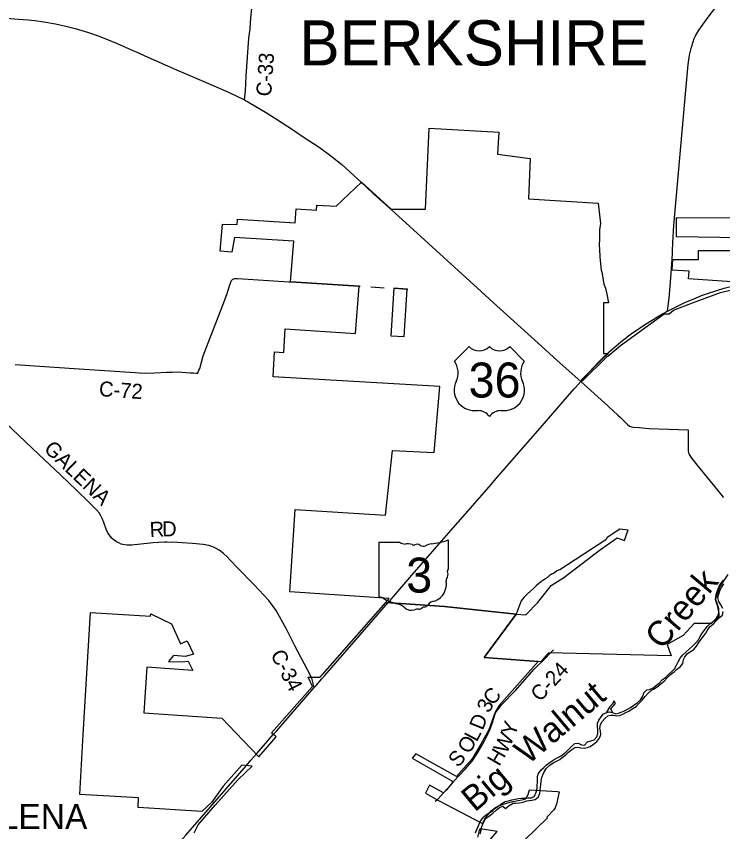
# Model space of a CAD drawing. Extents: x 1674899 to 2057726, y 653888 to 988278.
# Drawn here: x 1855438 to 1869524, y 809139 to 825391 of the extents above; entities that cross this region are included whole.
import ezdxf

# ---------------------------------------------------------------- set-up
doc = ezdxf.new("R2010")
doc.units = 0
for name, color, linetype in [('GM_X_Corporation', 7, 'Continuous'), ('GM_X_Corporation_Text', 7, 'Continuous'), ('GM_X_County_Road', 7, 'Continuous'), ('GM_X_County_Road_Text', 7, 'Continuous'), ('GM_X_Major_River', 7, 'Continuous'), ('GM_X_Major_River_Text', 7, 'Continuous'), ('GM_X_State_Location', 7, 'Continuous'), ('GM_X_State_Route', 7, 'Continuous'), ('GM_X_State_Shield', 7, 'Continuous'), ('GM_X_Township_Text', 7, 'Continuous'), ('GM_X_US_Location', 7, 'Continuous'), ('GM_X_US_Route', 7, 'Continuous'), ('GM_X_US_Shield', 7, 'Continuous'), ('SH_Data', 7, 'Continuous')]:
    doc.layers.add(name, color=color, linetype=linetype)

msp = doc.modelspace()

# ---------------------------------------------------------------- linework, layer by layer
at = {"layer": 'GM_X_Corporation'}
for points in [[(1869626, 814263), (1869472, 814042), (1869383, 813776), (1869438, 813593), (1869447, 813422), (1869302, 813286), (1868954, 813287), (1868735, 813050), (1868415, 812867), (1868495, 812643), (1866054, 812701), (1865997, 812642), (1865896, 812527), (1865843, 812531), (1864768, 812610), (1865403, 813477), (1863975, 813629), (1862805, 813710), (1862871, 813787), (1860894, 813922), (1860996, 815560), (1862803, 815449), (1862941, 816737), (1863769, 816697), (1863883, 818014), (1860562, 818202), (1860587, 818701), (1860771, 818691), (1860802, 819164), (1862199, 819069), (1862276, 820013), (1860906, 820099), (1860970, 820906), (1859791, 820983), (1859738, 820687), (1859505, 820707), (1859552, 821251), (1859841, 821244), (1859848, 821345), (1860999, 821277), (1861021, 821551), (1861422, 821527), (1861430, 821628), (1861816, 821605), (1862321, 822084), (1862912, 821546), (1863596, 821544), (1863668, 823164), (1865058, 823080), (1865034, 822645), (1865687, 822560), (1865651, 821750), (1867041, 821665), (1867085, 821260), (1867068, 821136), (1867065, 820962), (1867060, 820821), (1867068, 820747), (1867072, 820594), (1867087, 820460), (1867100, 820333), (1867115, 820300), (1867151, 820053), (1867187, 819974), (1867212, 819855), (1867245, 819678), (1867145, 819678), (1867148, 818668), (1867246, 818668), (1867161, 818594), (1866699, 818140), (1866722, 818118), (1867219, 818607), (1867231, 818617), (1867484, 818828), (1868360, 819462), (1868454, 819464), (1868541, 819536), (1868921, 819679), (1869480, 819883), (1869917, 819994)], [(1869899, 820974), (1868600, 820997), (1868600, 821384), (1871245, 821376)], [(1869899, 820085), (1868844, 820159), (1868852, 820309), (1868513, 820332), (1868528, 820542), (1869039, 820542), (1869039, 820726), (1869899, 820726)], [(1858983, 809113), (1859065, 809276), (1859404, 809666), (1859863, 810176), (1860139, 810448), (1859933, 810468), (1859566, 810043), (1859327, 809721), (1859138, 809540), (1857865, 809621), (1857876, 809816), (1856704, 809881), (1856773, 811076), (1856914, 813505), (1858114, 813436), (1858118, 813482), (1858535, 813283), (1858712, 812884), (1858845, 812940), (1858970, 812675), (1858813, 812629), (1858574, 812648), (1858471, 812534), (1858741, 812523), (1858864, 812540), (1858957, 812354), (1858043, 812416), (1857978, 811505), (1859535, 811404), (1859815, 811112), (1860275, 810628), (1860621, 811028), (1860529, 811110), (1861344, 812036), (1861260, 812216), (1861498, 812216), (1862805, 813710), (1863975, 813629), (1865403, 813477), (1864768, 812610), (1865843, 812531), (1865065, 811655), (1864989, 811518), (1864863, 811170), (1864701, 810884), (1864525, 810591), (1864418, 810465), (1864215, 810236), (1863402, 810688), (1863333, 810602), (1864120, 810151), (1864151, 810133), (1864012, 809966), (1863958, 809914), (1863680, 810064), (1863595, 809906), (1863859, 809760), (1864733, 809304), (1864786, 809405), (1864823, 809458), (1864864, 809499), (1864909, 809555), (1864976, 809609), (1865042, 809648), (1865212, 809706), (1865339, 809742), (1865409, 809752), (1865553, 809778), (1865590, 809795), (1865610, 809820), (1865642, 809877), (1865672, 809975), (1866230, 809941), (1866265, 809936), (1866212, 809686), (1866193, 809633), (1866180, 809613), (1866156, 809577), (1866016, 809430), (1866027, 809418), (1865570, 808968)], [(1864871, 808960), (1865028, 809140), (1864686, 809196), (1864670, 809164), (1864633, 809031)]]:
    msp.add_lwpolyline(points, dxfattribs=at)
for points in [[(1862906, 819024), (1863171, 819007), (1863230, 819954), (1862964, 819970)], [(1865403, 813477), (1865595, 813463), (1865838, 813709), (1866105, 814049), (1866357, 814208), (1867086, 814766), (1867421, 814993), (1867566, 814942), (1867606, 815063), (1867642, 815146), (1867470, 815167), (1867221, 815005), (1867191, 814953), (1866273, 814357), (1866252, 814350), (1866224, 814337), (1866188, 814318), (1866148, 814284), (1866111, 814270), (1866070, 814243), (1866027, 814208), (1865989, 814179), (1865937, 814144), (1865899, 814117), (1865853, 814081), (1865802, 814037), (1865749, 813986), (1865694, 813935), (1865628, 813870), (1865561, 813807), (1865503, 813738)]]:
    msp.add_lwpolyline(points, close=True, dxfattribs=at)
at = {"layer": 'GM_X_County_Road'}
for points in [[(1859988, 823723), (1860006, 823907), (1860023, 824199), (1860075, 824953), (1860102, 825144), (1860114, 825358), (1860137, 825544)], [(1855415, 818448), (1856692, 818365), (1857805, 818293), (1857887, 818287), (1857997, 818281), (1858195, 818286), (1858439, 818296), (1858547, 818299), (1858647, 818302), (1858736, 818299), (1858909, 818286), (1858969, 818282), (1859024, 818279), (1859060, 818281), (1859080, 818337), (1859095, 818374), (1859163, 818625), (1859262, 818885), (1859464, 819395), (1859545, 819601), (1859637, 819846), (1859697, 820038), (1859727, 820125), (1859753, 820151), (1859775, 820161), (1859787, 820164), (1859852, 820165), (1860873, 820101)], [(1860873, 820101), (1860906, 820099), (1862276, 820013), (1862296, 820012)], [(1862506, 819999), (1862509, 819999), (1862770, 819982)], [(1862980, 819969), (1863230, 819954), (1863244, 819953)], [(1857182, 815299), (1857153, 815378), (1857124, 815436), (1857089, 815491), (1857039, 815553), (1856865, 815727), (1856650, 815933), (1856316, 816250), (1855886, 816655), (1854135, 818318), (1853948, 818496), (1853892, 818538)], [(1858745, 814899), (1858660, 814905), (1858449, 814910), (1858391, 814909), (1858164, 814898), (1857861, 814864), (1857798, 814856), (1857739, 814849), (1857648, 814850), (1857559, 814865), (1857530, 814873), (1857479, 814893), (1857433, 814917), (1857388, 814948), (1857347, 814984), (1857307, 815028), (1857257, 815108), (1857229, 815169), (1857182, 815299)], [(1861324, 812212), (1861236, 812378), (1860992, 812846), (1860828, 813174), (1860617, 813548), (1860476, 813746), (1860173, 814063), (1859848, 814400), (1859708, 814543), (1859640, 814615), (1859568, 814682), (1859482, 814748), (1859421, 814784), (1859356, 814815), (1859277, 814840), (1859165, 814861), (1858949, 814884), (1858745, 814899)], [(1864113, 810086), (1864158, 810136), (1864387, 810382), (1864526, 810545), (1864640, 810718), (1864769, 810937), (1864875, 811146), (1864930, 811298), (1864995, 811506), (1865050, 811588), (1865117, 811671), (1865392, 811956), (1865763, 812377), (1866002, 812614)], [(1866002, 812614), (1866066, 812677), (1866122, 812737), (1866148, 812764)], [(1861379, 812013), (1861332, 812198), (1861324, 812212)], [(1863902, 809854), (1863958, 809914), (1864113, 810086)], [(1863789, 809745), (1863841, 809789), (1863902, 809854)]]:
    msp.add_lwpolyline(points, dxfattribs=at)
at = {"layer": 'GM_X_Major_River'}
for points in [[(1868988, 812905), (1869040, 812965), (1869073, 813027), (1869117, 813093), (1869163, 813157), (1869214, 813227), (1869270, 813284), (1869341, 813338), (1869399, 813392), (1869439, 813458), (1869446, 813522), (1869436, 813586), (1869422, 813650), (1869403, 813701), (1869381, 813767), (1869385, 813833), (1869410, 813905), (1869432, 813979), (1869455, 814033), (1869485, 814085), (1869539, 814155)], [(1869524, 813590), (1869486, 813662), (1869445, 813729), (1869429, 813805), (1869446, 813873), (1869470, 813941), (1869498, 814009), (1869549, 814079)], [(1869004, 812835), (1869046, 812909), (1869096, 812975), (1869145, 813043), (1869185, 813095), (1869229, 813166), (1869272, 813228), (1869338, 813280), (1869399, 813346), (1869457, 813406), (1869517, 813453), (1869532, 813526)], [(1864597, 809114), (1864622, 809180), (1864648, 809242), (1864677, 809308), (1864701, 809362), (1864759, 809432), (1864822, 809487), (1864892, 809531), (1864942, 809559), (1865002, 809615), (1865065, 809664), (1865117, 809702), (1865189, 809742), (1865253, 809755), (1865321, 809773), (1865383, 809787), (1865449, 809802), (1865512, 809810), (1865580, 809810), (1865646, 809811), (1865714, 809813), (1865774, 809845), (1865804, 809929), (1865821, 809997), (1865827, 810061), (1865833, 810123), (1865832, 810191), (1865832, 810245), (1865848, 810299), (1865903, 810369), (1865957, 810417), (1866007, 810463), (1866060, 810507), (1866126, 810554), (1866186, 810588), (1866260, 810628), (1866327, 810669), (1866395, 810727), (1866447, 810775), (1866510, 810839), (1866578, 810898), (1866642, 810900), (1866708, 810868), (1866770, 810865), (1866826, 810933), (1866892, 810947), (1866958, 810968), (1867011, 811030), (1867033, 811094), (1867034, 811162), (1867028, 811235), (1867026, 811301), (1867055, 811361), (1867099, 811425), (1867147, 811487), (1867198, 811510), (1867262, 811528), (1867326, 811514), (1867392, 811491), (1867444, 811501), (1867496, 811519), (1867566, 811550), (1867626, 811578), (1867684, 811616), (1867755, 811661), (1867821, 811707), (1867883, 811765), (1867930, 811839), (1867950, 811907), (1868010, 811963), (1868064, 811972), (1868137, 812008), (1868187, 812044), (1868255, 812100), (1868318, 812163), (1868388, 812221), (1868450, 812279), (1868507, 812331), (1868565, 812388), (1868603, 812460), (1868634, 812522), (1868676, 812598), (1868732, 812662), (1868789, 812718), (1868859, 812786), (1868922, 812839), (1868988, 812905)], [(1864689, 809093), (1864706, 809167), (1864722, 809239), (1864742, 809289), (1864765, 809347), (1864803, 809409), (1864875, 809453), (1864938, 809505), (1865004, 809568), (1865072, 809624), (1865139, 809648), (1865196, 809599), (1865267, 809659), (1865343, 809709), (1865393, 809710), (1865469, 809712), (1865545, 809728), (1865615, 809751), (1865665, 809759), (1865719, 809769), (1865787, 809782), (1865850, 809836), (1865878, 809906), (1865881, 809974), (1865889, 810024), (1865895, 810076), (1865902, 810143), (1865920, 810217), (1865934, 810271), (1865967, 810335), (1866011, 810405), (1866079, 810468), (1866144, 810510), (1866212, 810546), (1866274, 810581), (1866324, 810619), (1866393, 810671), (1866451, 810725), (1866515, 810775), (1866578, 810818), (1866630, 810822), (1866693, 810808), (1866763, 810803), (1866828, 810819), (1866878, 810839), (1866946, 810884), (1867012, 810936), (1867065, 811002), (1867091, 811074), (1867087, 811142), (1867074, 811204), (1867084, 811272), (1867119, 811336), (1867173, 811392), (1867231, 811446), (1867295, 811464), (1867347, 811463), (1867415, 811445), (1867465, 811453), (1867533, 811478), (1867594, 811512), (1867650, 811538), (1867718, 811587), (1867796, 811632), (1867857, 811698), (1867919, 811761), (1867980, 811833), (1868040, 811902), (1868104, 811962), (1868158, 811987), (1868243, 812048), (1868289, 812089), (1868359, 812141), (1868418, 812205), (1868482, 812273), (1868553, 812328), (1868603, 812370), (1868675, 812424), (1868732, 812492), (1868742, 812568), (1868770, 812622), (1868823, 812690), (1868897, 812735), (1868951, 812773), (1869004, 812835)], [(1867326, 811514), (1867293, 811587), (1867339, 811640), (1867389, 811692), (1867359, 811750), (1867323, 811680), (1867269, 811621), (1867198, 811510)], [(1867198, 811510), (1867262, 811528), (1867326, 811514)]]:
    msp.add_lwpolyline(points, dxfattribs=at)
at = {"layer": 'GM_X_State_Route'}
for points in [[(1868532, 820875), (1868550, 821219), (1868792, 823921), (1868838, 824429), (1868865, 824617), (1868879, 824699), (1868899, 824776), (1868933, 824884), (1868958, 824946), (1868978, 824987), (1869049, 825113), (1869236, 825376), (1869514, 825748)], [(1868523, 820718), (1868532, 820875)], [(1868515, 820560), (1868520, 820663), (1868523, 820718)], [(1868423, 819513), (1868436, 819621), (1868455, 819771), (1868478, 820007), (1868509, 820452), (1868515, 820560)], [(1866346, 817716), (1866565, 817968), (1866588, 817993)], [(1866588, 817993), (1866693, 818111)], [(1866693, 818111), (1867234, 817626), (1867256, 817606)], [(1864967, 816131), (1865275, 816485), (1865884, 817183), (1866346, 817716)], [(1867256, 817606), (1867435, 817444), (1867478, 817401)], [(1867478, 817401), (1867625, 817254), (1867664, 817220), (1867706, 817207), (1867748, 817201), (1867855, 817194)], [(1867855, 817194), (1867983, 817185), (1868056, 817177)], [(1868056, 817177), (1868448, 817163), (1868836, 817146)], [(1868836, 817146), (1868837, 816776)], [(1868837, 816776), (1868837, 816721), (1868851, 816673), (1868887, 816606), (1869030, 816427), (1869071, 816377)], [(1869071, 816377), (1869420, 815948), (1869509, 815839), (1869530, 815808), (1869534, 815802)], [(1862967, 813834), (1863287, 814202), (1863966, 814984), (1864395, 815476), (1864911, 816067), (1864967, 816131)], [(1861588, 812249), (1862256, 813018), (1862855, 813706), (1862898, 813755)], [(1862898, 813755), (1862922, 813783), (1862967, 813834)], [(1861414, 812052), (1861532, 812184), (1861588, 812249)], [(1860617, 811135), (1860632, 811151), (1860959, 811525), (1861379, 812013), (1861414, 812052)], [(1860234, 810698), (1860366, 810850), (1860563, 811079), (1860617, 811135)], [(1860025, 810459), (1860116, 810563), (1860234, 810698)], [(1853225, 794338), (1854573, 800349), (1855512, 804546), (1855541, 804679), (1855596, 804898), (1855689, 805139), (1855836, 805465), (1855908, 805599), (1856008, 805767), (1856148, 805978), (1856255, 806119), (1856504, 806413), (1857597, 807668), (1858467, 808668), (1858818, 809072), (1859440, 809788), (1860025, 810459)]]:
    msp.add_lwpolyline(points, dxfattribs=at)
at = {"layer": 'GM_X_State_Shield'}
for p, q in [((1862667, 814887), (1862667, 813831)), ((1863089, 814906), (1862681, 814906)), ((1864059, 814379), (1864059, 814932)), ((1864059, 814379), (1864059, 814379))]:
    msp.add_line(p, q, dxfattribs=at)
for centre, radius, start, end in [((1862683, 814890), 16.1, 98.1301, 188.1301), ((1863186, 815028), 156, 231.6195, 271.1119), ((1863564, 816346), 1476, 275.8445, 288.9065), ((1864044, 814934), 15.5, 351.8621, 97.738), ((1863238, 814312), 562, 80.4867, 94.9883), ((1863365, 814895), 45.1, 219.7921, 297.1024), ((1863431, 814773), 93.8, 54.4667, 119.1411), ((1863553, 814940), 113, 233.8562, 294.8282), ((1863752, 814583), 297, 97.3462, 120.7689), ((1864056, 814338), 24, 107.944, 210.337), ((1863903, 814269), 144, 340.033, 23.6496), ((1864043, 814377), 16.6, 289.6038, 7.7341), ((1863646, 814077), 369, 292.3089, 8.9858), ((1864115, 814148), 105, 136.8065, 186.9296), ((1862683, 813828), 16.3, 171.9584, 258.3066), ((1862686, 813937), 124, 267.339, 280.6039), ((1862711, 813770), 44.8, 29.7484, 93.2717), ((1863277, 814719), 1066, 240.4129, 257.1985), ((1862959, 813356), 334, 47.1842, 75.836), ((1863319, 813765), 212, 230.7004, 286.2918), ((1863457, 813685), 113, 268.777, 315.5493), ((1863559, 813583), 31.8, 65.7517, 132.6484), ((1863546, 813728), 119, 282.8732, 323.2771), ((1863802, 813534), 202, 94.4031, 142.5768), ((1863442, 813399), 174, 85.6951, 111.2099)]:
    msp.add_arc(centre, radius, start, end, dxfattribs=at)
at = {"layer": 'GM_X_US_Route'}
for points in [[(1855037, 825370), (1855173, 825360), (1855248, 825354), (1855476, 825337), (1855674, 825320), (1855808, 825306), (1855988, 825281), (1856219, 825240), (1856454, 825186), (1856610, 825146), (1856879, 825067), (1857093, 824992), (1857448, 824848), (1857746, 824717), (1857872, 824661)], [(1857872, 824661), (1858002, 824603), (1858452, 824407), (1858634, 824327), (1858849, 824233), (1859315, 824029), (1859681, 823869), (1859988, 823723), (1860406, 823477), (1860588, 823365), (1860963, 823124), (1861157, 822990), (1861474, 822783), (1861713, 822608), (1861927, 822435), (1862088, 822291), (1862329, 822071), (1862359, 822043)], [(1862359, 822043), (1862416, 821990), (1862570, 821847), (1862984, 821471)], [(1862984, 821471), (1864255, 820317), (1864708, 819903), (1864947, 819685), (1865843, 818874), (1866225, 818531)], [(1868423, 819513), (1868530, 819569), (1868780, 819692), (1868932, 819756), (1869103, 819824), (1869240, 819873), (1869556, 819971), (1869772, 820024)], [(1867232, 818676), (1867261, 818703), (1867495, 818904), (1867708, 819068), (1867816, 819145), (1867983, 819256), (1868226, 819404), (1868324, 819459), (1868423, 819513)], [(1867046, 818494), (1867142, 818593), (1867232, 818676)], [(1866225, 818531), (1866693, 818111)], [(1866761, 818189), (1866781, 818212), (1866860, 818300), (1867046, 818494)], [(1866693, 818111), (1866761, 818189)]]:
    msp.add_lwpolyline(points, dxfattribs=at)
at = {"layer": 'GM_X_US_Shield'}
for p, q in [((1864465, 818808), (1864175, 818518)), ((1865567, 818518), (1865277, 818808)), ((1864581, 817532), (1864639, 817532)), ((1865103, 817532), (1865161, 817532))]:
    msp.add_line(p, q, dxfattribs=at)
for centre, radius, start, end in [((1864668, 819015), 290, 225.573, 314.427), ((1865074, 819015), 290, 225.573, 314.427), ((1863842, 818285), 406, 334.5471, 35.0009), ((1865900, 818285), 406, 144.9991, 205.4529), ((1864576, 817938), 406, 154.8319, 270.6383), ((1865165, 817938), 406, 269.3617, 25.1681), ((1864639, 817242), 290, 36.8699, 90), ((1865103, 817242), 290, 90, 143.1301)]:
    msp.add_arc(centre, radius, start, end, dxfattribs=at)
at = {"layer": 'SH_Data'}
for points in [[(1855037, 825370), (1855173, 825360), (1855248, 825354), (1855476, 825337), (1855674, 825320), (1855808, 825306), (1855988, 825281), (1856219, 825240), (1856454, 825186), (1856610, 825146), (1856879, 825067), (1857093, 824992), (1857448, 824848), (1857746, 824717), (1857872, 824661)], [(1857872, 824661), (1858002, 824603), (1858452, 824407), (1858634, 824327), (1858849, 824233), (1859315, 824029), (1859681, 823869), (1859988, 823723), (1860406, 823477), (1860588, 823365), (1860963, 823124), (1861157, 822990), (1861474, 822783), (1861713, 822608), (1861927, 822435), (1862088, 822291), (1862329, 822071), (1862359, 822043)], [(1862359, 822043), (1862416, 821990), (1862570, 821847), (1862984, 821471)], [(1862984, 821471), (1864255, 820317), (1864708, 819903), (1864947, 819685), (1865843, 818874), (1866225, 818531)], [(1868423, 819513), (1868530, 819569), (1868780, 819692), (1868932, 819756), (1869103, 819824), (1869240, 819873), (1869556, 819971), (1869772, 820024)], [(1867232, 818676), (1867261, 818703), (1867495, 818904), (1867708, 819068), (1867816, 819145), (1867983, 819256), (1868226, 819404), (1868324, 819459), (1868423, 819513)], [(1867046, 818494), (1867142, 818593), (1867232, 818676)], [(1866225, 818531), (1866693, 818111)], [(1866761, 818189), (1866781, 818212), (1866860, 818300), (1867046, 818494)], [(1866693, 818111), (1866761, 818189)]]:
    msp.add_lwpolyline(points, dxfattribs=at)

# ---------------------------------------------------------------- texts
at = {"layer": 'GM_X_Corporation_Text'}
msp.add_text('GALENA', height=500, rotation=0, dxfattribs=at).set_placement((1854142, 809190))
at = {"layer": 'GM_X_County_Road_Text'}
for s, rotation, p in [('C-33', 85.8898, (1860518, 823787)), ('C-72', 355.8897, (1857079, 817822)), ('GALENA', 316.1398, (1855970, 816747)), ('R', 2.8581, (1858104, 815010)), ('D', 1.2131, (1858348, 815022)), ('C-34', 297.3324, (1860498, 812674)), ('C-24', 46.9258, (1865881, 811713)), ('C', 49.6193, (1864941, 811638)), ('3', 62.7391, (1864867, 811489)), ('D', 68.3775, (1864739, 811146)), ('Y', 70.9367, (1865379, 811024)), ('O', 58.1433, (1864468, 810671)), ('L', 61.989, (1864618, 810914)), ('W', 63.7906, (1865210, 810675)), ('S', 48.9106, (1864247, 810403)), ('H', 60.1864, (1865069, 810428))]:
    msp.add_text(s, height=300, rotation=rotation, dxfattribs=at).set_placement(p)
at = {"layer": 'GM_X_Major_River_Text'}
for s, rotation, p in [('Creek', 50.0025, (1868314, 812744)), ('Walnut', 40.0023, (1865638, 810458)), ('Big', 40.0016, (1864579, 809516))]:
    msp.add_text(s, height=500, rotation=rotation, dxfattribs=at).set_placement(p)
at = {"layer": 'GM_X_State_Location'}
for s in ['s', 'r']:
    msp.add_text(s, height=1, dxfattribs=at).set_placement((1863348, 814289))
msp.add_text('3', height=1, rotation=0, dxfattribs=at).set_placement((1863197, 814216))
at = {"layer": 'GM_X_State_Shield'}
msp.add_text('3', height=696, dxfattribs=at).set_placement((1863213, 813905))
at = {"layer": 'GM_X_Township_Text'}
msp.add_text('BERKSHIRE', height=900, rotation=0, dxfattribs=at).set_placement((1861082, 824412))
at = {"layer": 'GM_X_US_Location'}
for s in ['0', '/']:
    msp.add_text(s, height=1, dxfattribs=at).set_placement((1865947, 818572))
msp.add_text('36', height=1, rotation=0, dxfattribs=at).set_placement((1865740, 818365))
at = {"layer": 'GM_X_US_Shield'}
msp.add_text('36', height=696.1, dxfattribs=at).set_placement((1864457, 817793))

doc.saveas('drawing.dxf')
